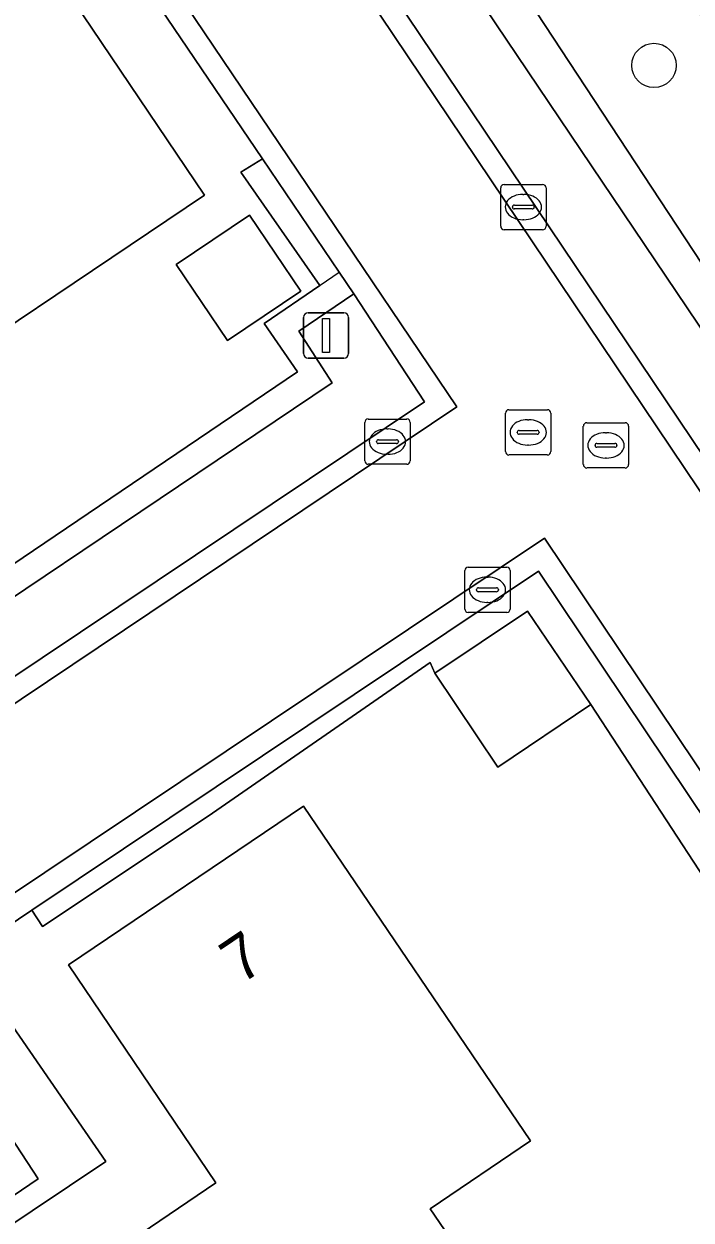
# Model space of a CAD drawing. Extents: x 158793 to 159888, y 384317 to 385256.
# Drawn here: x 158930.48 to 158945.21, y 384617.61 to 384644.03 of the extents above; entities that cross this region are included whole.
import ezdxf

# ---------------------------------------------------------------- set-up
doc = ezdxf.new("R2010")
doc.units = 0
for name, color, linetype in [('IMGEO_Boom', 7, 'Continuous'), ('IMGEO_Erf', 7, 'Continuous'), ('IMGEO_Groenvoorziening', 7, 'Continuous'), ('IMGEO_Haag', 7, 'Continuous'), ('IMGEO_Hek', 7, 'Continuous'), ('IMGEO_Kolk', 7, 'Continuous'), ('IMGEO_Lichtmast', 7, 'Continuous'), ('IMGEO_Pand', 7, 'Continuous'), ('IMGEO_Pand_nummerreeks', 7, 'Continuous'), ('IMGEO_Parkeervlak_open', 7, 'Continuous'), ('IMGEO_Rijbaan_lokaal_open', 7, 'Continuous'), ('IMGEO_Rioolput', 7, 'Continuous'), ('IMGEO_Voetpad_open', 7, 'Continuous')]:
    doc.layers.add(name, color=color, linetype=linetype)

msp = doc.modelspace()

# ---------------------------------------------------------------- linework, layer by layer
at = {"layer": 'IMGEO_Boom'}
msp.add_circle((158944.39, 384643.118), 0.489, dxfattribs=at)
at = {"layer": 'IMGEO_Erf'}
for points in [[(158935.269, 384640.755), (158935.742, 384641.055), (158931.239, 384647.707), (158930.053, 384646.895), (158926.376, 384644.46), (158920.02, 384653.654), (158917.65, 384657.141), (158903.486, 384647.632), (158905.26, 384644.832), (158899.805, 384640.906), (158909.685, 384626.219), (158910.802, 384626.858), (158911.256, 384626.177), (158922.042, 384633.454), (158922.226, 384633.163), (158925.099, 384628.623), (158936.517, 384636.347), (158935.783, 384637.416), (158937.012, 384638.256)], [(158933.838, 384638.715), (158935.46, 384639.808), (158936.59, 384638.131), (158934.968, 384637.038)]]:
    msp.add_lwpolyline(points, close=True, dxfattribs=at)
for points in [[(158924.575, 384644.51), (158926.138, 384642.19), (158930.948, 384645.466), (158934.462, 384640.251), (158927.06, 384635.272), (158926.167, 384636.6), (158925.827, 384636.371), (158925.241, 384637.242), (158922.204, 384635.199), (158920.865, 384637.19), (158919.342, 384636.067), (158919.879, 384635.339), (158916.324, 384632.791), (158915.823, 384633.472), (158915.091, 384632.933), (158913.616, 384635.123), (158911.211, 384633.503), (158907.976, 384638.304), (158904.737, 384643.112), (158907.129, 384644.742)], [(158948.959, 384619.868), (158942.998, 384628.997), (158940.94, 384627.612), (158939.55, 384629.69), (158939.449, 384629.925), (158934.543, 384626.53), (158930.884, 384624.093), (158930.65, 384624.451), (158929.151, 384623.447), (158932.282, 384618.903), (158921.737, 384611.84)], [(158932.239, 384616.753), (158934.715, 384618.426), (158931.463, 384623.249), (158936.651, 384626.748), (158941.663, 384619.361), (158939.449, 384617.854), (158941.719, 384614.519)]]:
    msp.add_lwpolyline(points, dxfattribs=at)
at = {"layer": 'IMGEO_Groenvoorziening'}
for points in [[(158939.017, 384653.792), (158935.807, 384651.605), (158936.203, 384651.016), (158937.049, 384651.521), (158951.101, 384630.138), (158952.761, 384631.247), (158949.979, 384635.355), (158950.928, 384636.006)], [(158936.203, 384651.016), (158950.52, 384629.75), (158951.101, 384630.138), (158937.049, 384651.521)], [(158937.281, 384636.103), (158936.543, 384637.243), (158937.764, 384638.068), (158937.439, 384638.548), (158935.742, 384641.055), (158935.269, 384640.755), (158937.012, 384638.256), (158935.783, 384637.416), (158936.517, 384636.347), (158925.099, 384628.623), (158925.43, 384628.137)], [(158954.158, 384623.366), (158953.415, 384624.464), (158948.9, 384621.402), (158941.838, 384631.945), (158930.65, 384624.451), (158930.884, 384624.093), (158934.543, 384626.53), (158939.449, 384629.925), (158939.55, 384629.69), (158941.596, 384631.059), (158942.998, 384628.997), (158948.959, 384619.868)], [(158919.186, 384616.765), (158918.336, 384616.199), (158921.296, 384611.545), (158921.737, 384611.84), (158932.282, 384618.903), (158929.151, 384623.447), (158928.046, 384622.707), (158930.79, 384618.521), (158925.79, 384615.12), (158922.031, 384612.574)]]:
    msp.add_lwpolyline(points, close=True, dxfattribs=at)
at = {"layer": 'IMGEO_Haag'}
for points in [[(158936.203, 384651.016), (158950.52, 384629.75), (158951.101, 384630.138), (158937.049, 384651.521)], [(158954.158, 384623.366), (158953.415, 384624.464), (158948.9, 384621.402), (158941.838, 384631.945), (158930.65, 384624.451), (158930.884, 384624.093), (158934.543, 384626.53), (158939.449, 384629.925), (158939.55, 384629.69), (158941.596, 384631.059), (158942.998, 384628.997), (158948.959, 384619.868)]]:
    msp.add_lwpolyline(points, close=True, dxfattribs=at)
at = {"layer": 'IMGEO_Hek'}
for points in [[(158905.26, 384644.832), (158899.805, 384640.906), (158909.685, 384626.219), (158910.802, 384626.858), (158911.256, 384626.177), (158922.042, 384633.454), (158922.226, 384633.163), (158925.099, 384628.623), (158936.517, 384636.347), (158935.783, 384637.416)], [(158935.783, 384637.416), (158937.439, 384638.548)]]:
    msp.add_lwpolyline(points, dxfattribs=at)
at = {"layer": 'IMGEO_Kolk'}
for p, q in [((158941.004, 384639.562), (158941.004, 384640.414)), ((158941.079, 384640.488), (158941.931, 384640.488)), ((158942.005, 384640.414), (158942.005, 384639.562)), ((158941.492, 384640.268), (158941.517, 384640.268)), ((158941.263, 384639.982), (158941.263, 384639.994)), ((158941.701, 384639.945), (158941.303, 384639.945)), ((158941.306, 384640.031), (158941.704, 384640.031)), ((158941.747, 384639.994), (158941.747, 384639.982)), ((158941.515, 384639.708), (158941.49, 384639.708)), ((158941.931, 384639.488), (158941.079, 384639.488)), ((158938.078, 384635.305), (158938.93, 384635.305)), ((158938.003, 384634.379), (158938.003, 384635.231)), ((158938.491, 384635.085), (158938.516, 384635.085)), ((158939.004, 384635.231), (158939.004, 384634.379)), ((158938.262, 384634.799), (158938.262, 384634.811)), ((158938.7, 384634.762), (158938.302, 384634.762)), ((158938.305, 384634.848), (158938.703, 384634.848)), ((158938.746, 384634.811), (158938.746, 384634.799)), ((158938.514, 384634.525), (158938.489, 384634.525)), ((158938.93, 384634.305), (158938.078, 384634.305)), ((158940.211, 384631.107), (158940.211, 384631.959)), ((158940.286, 384632.033), (158941.138, 384632.033)), ((158941.212, 384631.959), (158941.212, 384631.107)), ((158940.699, 384631.813), (158940.724, 384631.813)), ((158940.47, 384631.527), (158940.47, 384631.539)), ((158940.908, 384631.49), (158940.51, 384631.49)), ((158940.513, 384631.576), (158940.911, 384631.576)), ((158940.954, 384631.539), (158940.954, 384631.527)), ((158940.722, 384631.253), (158940.697, 384631.253)), ((158941.138, 384631.033), (158940.286, 384631.033))]:
    msp.add_line(p, q, dxfattribs=at)
for points in [[(158941.004, 384639.562), (158941.004, 384640.414)], [(158941.079, 384640.488), (158941.931, 384640.488)], [(158942.005, 384640.414), (158942.005, 384639.562)], [(158941.931, 384639.488), (158941.079, 384639.488)], [(158938.078, 384635.305), (158938.93, 384635.305)], [(158938.003, 384634.379), (158938.003, 384635.231)], [(158939.004, 384635.231), (158939.004, 384634.379)], [(158938.93, 384634.305), (158938.078, 384634.305)], [(158940.211, 384631.107), (158940.211, 384631.959)], [(158940.286, 384632.033), (158941.138, 384632.033)], [(158941.212, 384631.959), (158941.212, 384631.107)], [(158941.138, 384631.033), (158940.286, 384631.033)]]:
    msp.add_lwpolyline(points, dxfattribs=at)
for centre, radius, start, end in [((158941.081, 384640.412), 0.0765, 91.552, 178.448), ((158941.081, 384640.412), 0.0765, 91.552, 178.448), ((158941.929, 384640.412), 0.0765, 1.552, 88.448), ((158941.929, 384640.412), 0.0765, 1.552, 88.448), ((158941.303, 384639.991), 0.0403, 85.8775, 175.7526), ((158941.3, 384639.981), 0.0366, 178.938, 274.7102), ((158941.704, 384639.988), 0.043, 264.8664, 352.4533), ((158941.708, 384639.993), 0.0386, 1.7309, 96.639), ((158941.081, 384639.564), 0.0765, 181.552, 268.448), ((158941.081, 384639.564), 0.0765, 181.552, 268.448), ((158941.929, 384639.564), 0.0765, 271.552, 358.448), ((158941.929, 384639.564), 0.0765, 271.552, 358.448), ((158938.08, 384635.229), 0.0765, 91.552, 178.448), ((158938.08, 384635.229), 0.0765, 91.552, 178.448), ((158938.928, 384635.229), 0.0765, 1.552, 88.448), ((158938.928, 384635.229), 0.0765, 1.552, 88.448), ((158938.302, 384634.808), 0.0403, 85.8775, 175.7526), ((158938.299, 384634.798), 0.0366, 178.938, 274.7102), ((158938.703, 384634.805), 0.043, 264.8664, 352.4533), ((158938.707, 384634.81), 0.0386, 1.7309, 96.639), ((158938.08, 384634.381), 0.0765, 181.552, 268.448), ((158938.08, 384634.381), 0.0765, 181.552, 268.448), ((158938.928, 384634.381), 0.0765, 271.552, 358.448), ((158938.928, 384634.381), 0.0765, 271.552, 358.448), ((158940.288, 384631.957), 0.0765, 91.552, 178.448), ((158940.288, 384631.957), 0.0765, 91.552, 178.448), ((158941.136, 384631.957), 0.0765, 1.552, 88.448), ((158941.136, 384631.957), 0.0765, 1.552, 88.448), ((158940.51, 384631.536), 0.0403, 85.8775, 175.7526), ((158940.507, 384631.526), 0.0366, 178.938, 274.7102), ((158940.911, 384631.533), 0.043, 264.8664, 352.4533), ((158940.915, 384631.538), 0.0386, 1.7309, 96.639), ((158940.288, 384631.109), 0.0765, 181.552, 268.448), ((158940.288, 384631.109), 0.0765, 181.552, 268.448), ((158941.136, 384631.109), 0.0765, 271.552, 358.448), ((158941.136, 384631.109), 0.0765, 271.552, 358.448)]:
    msp.add_arc(centre, radius, start, end, dxfattribs=at)
for centre, major_axis, ratio, start_param, end_param in [((158941.491, 384639.988), (-0.387, 0.002), 0.722429, 4.712389, 7.853982), ((158941.516, 384639.988), (-0.39, 0.002), 0.717154, 1.570796, 4.712389), ((158938.49, 384634.805), (-0.387, 0.002), 0.722429, 4.712389, 7.853982), ((158938.515, 384634.805), (-0.39, 0.002), 0.717154, 1.570796, 4.712389), ((158940.698, 384631.533), (-0.387, 0.002), 0.722429, 4.712389, 7.853982), ((158940.723, 384631.533), (-0.39, 0.002), 0.717154, 1.570796, 4.712389)]:
    msp.add_ellipse(centre, major_axis=major_axis, ratio=ratio, start_param=start_param, end_param=end_param, dxfattribs=at)
at = {"layer": 'IMGEO_Lichtmast'}
for p, q in [((158936.652, 384636.751), (158936.652, 384637.551)), ((158936.652, 384637.551), (158936.652, 384636.751)), ((158936.752, 384637.651), (158937.542, 384637.651)), ((158937.542, 384637.651), (158936.752, 384637.651)), ((158937.642, 384637.551), (158937.642, 384636.751)), ((158937.642, 384636.751), (158937.642, 384637.551)), ((158937.542, 384636.651), (158936.752, 384636.651)), ((158936.752, 384636.651), (158937.542, 384636.651))]:
    msp.add_line(p, q, dxfattribs=at)
msp.add_lwpolyline([(158937.072, 384637.526), (158937.222, 384637.526), (158937.222, 384636.776), (158937.072, 384636.776), (158937.072, 384637.526)], dxfattribs=at)
for centre, start, end in [((158936.752, 384637.551), 90, 180), ((158936.752, 384637.551), 90, 180), ((158937.542, 384637.551), 0, 90), ((158937.542, 384637.551), 360, 90), ((158936.752, 384636.751), 180, 270), ((158936.752, 384636.751), 180, 270), ((158937.542, 384636.751), 270, 0), ((158937.542, 384636.751), 270, 0)]:
    msp.add_arc(centre, 0.1, start, end, dxfattribs=at)
at = {"layer": 'IMGEO_Pand'}
for points in [[(158930.948, 384645.466), (158926.138, 384642.19), (158924.575, 384644.51), (158918.797, 384640.665), (158921.037, 384637.317), (158920.865, 384637.19), (158922.204, 384635.199), (158925.241, 384637.242), (158925.827, 384636.371), (158926.167, 384636.6), (158927.06, 384635.272), (158934.462, 384640.251)], [(158933.838, 384638.715), (158934.968, 384637.038), (158936.59, 384638.131), (158935.46, 384639.808)], [(158941.596, 384631.059), (158939.55, 384629.69), (158940.94, 384627.612), (158942.998, 384628.997)], [(158931.463, 384623.249), (158934.715, 384618.426), (158932.239, 384616.753), (158936.087, 384611.18), (158939.564, 384613.58), (158939.81, 384613.244), (158941.719, 384614.519), (158939.449, 384617.854), (158941.663, 384619.361), (158936.651, 384626.748)]]:
    msp.add_lwpolyline(points, close=True, dxfattribs=at)
at = {"layer": 'IMGEO_Parkeervlak_open'}
msp.add_lwpolyline([(158928.046, 384622.707), (158919.186, 384616.765), (158922.031, 384612.574), (158925.79, 384615.12), (158930.79, 384618.521)], close=True, dxfattribs=at)
at = {"layer": 'IMGEO_Rijbaan_lokaal_open'}
for points in [[(158920.881, 384670.173), (158923.955, 384665.633), (158949.957, 384626.932), (158968.418, 384639.524), (158968.134, 384639.947), (158950.085, 384627.638), (158924.353, 384665.905), (158921.285, 384670.455)], [(158941.972, 384632.67), (158949.064, 384622.099), (158970.35, 384636.65), (158968.418, 384639.524), (158949.957, 384626.932), (158923.955, 384665.633), (158920.881, 384670.173)], [(158920.527, 384663.541), (158921.052, 384662.795), (158921.38, 384662.329), (158923.499, 384659.163), (158924.01, 384658.409), (158927.045, 384653.945), (158927.544, 384653.21), (158930.702, 384648.501), (158931.239, 384647.707), (158935.742, 384641.055), (158937.439, 384638.548), (158937.764, 384638.068), (158939.325, 384635.681), (158916.548, 384620.432), (158916.491, 384620.393), (158916.788, 384619.978), (158916.847, 384620.015), (158940.033, 384635.577), (158921.019, 384663.762)], [(158921.019, 384663.762), (158940.033, 384635.577), (158916.847, 384620.015), (158916.788, 384619.978), (158918.623, 384617.027), (158918.871, 384617.212), (158941.972, 384632.67)]]:
    msp.add_lwpolyline(points, dxfattribs=at)
msp.add_lwpolyline([(158941.972, 384632.67), (158918.871, 384617.212), (158919.186, 384616.765), (158928.046, 384622.707), (158929.151, 384623.447), (158930.65, 384624.451), (158941.838, 384631.945), (158948.9, 384621.402), (158953.415, 384624.464), (158955.406, 384625.815), (158956.071, 384626.266), (158960.669, 384629.404), (158961.404, 384629.901), (158968.085, 384634.504), (158968.774, 384634.969), (158970.621, 384636.247), (158970.35, 384636.65), (158949.064, 384622.099)], close=True, dxfattribs=at)
at = {"layer": 'IMGEO_Rioolput'}
for p, q in [((158941.111, 384634.584), (158941.111, 384635.436)), ((158941.186, 384635.51), (158942.038, 384635.51)), ((158941.599, 384635.29), (158941.624, 384635.29)), ((158942.112, 384635.436), (158942.112, 384634.584)), ((158941.413, 384635.053), (158941.811, 384635.053)), ((158942.829, 384634.297), (158942.829, 384635.149)), ((158942.904, 384635.223), (158943.756, 384635.223)), ((158943.83, 384635.149), (158943.83, 384634.297)), ((158941.37, 384635.004), (158941.37, 384635.016)), ((158941.808, 384634.967), (158941.41, 384634.967)), ((158941.854, 384635.016), (158941.854, 384635.004)), ((158943.131, 384634.766), (158943.529, 384634.766)), ((158943.317, 384635.003), (158943.342, 384635.003)), ((158942.038, 384634.51), (158941.186, 384634.51)), ((158941.622, 384634.73), (158941.597, 384634.73)), ((158943.088, 384634.717), (158943.088, 384634.729)), ((158943.526, 384634.68), (158943.128, 384634.68)), ((158943.572, 384634.729), (158943.572, 384634.717)), ((158943.34, 384634.443), (158943.315, 384634.443)), ((158943.756, 384634.223), (158942.904, 384634.223))]:
    msp.add_line(p, q, dxfattribs=at)
for points in [[(158941.111, 384634.584), (158941.111, 384635.436)], [(158941.186, 384635.51), (158942.038, 384635.51)], [(158942.112, 384635.436), (158942.112, 384634.584)], [(158942.829, 384634.297), (158942.829, 384635.149)], [(158942.904, 384635.223), (158943.756, 384635.223)], [(158943.83, 384635.149), (158943.83, 384634.297)], [(158942.038, 384634.51), (158941.186, 384634.51)], [(158943.756, 384634.223), (158942.904, 384634.223)]]:
    msp.add_lwpolyline(points, dxfattribs=at)
for centre, radius, start, end in [((158941.188, 384635.434), 0.0765, 91.552, 178.448), ((158941.188, 384635.434), 0.0765, 91.552, 178.448), ((158942.036, 384635.434), 0.0765, 1.552, 88.448), ((158942.036, 384635.434), 0.0765, 1.552, 88.448), ((158941.41, 384635.013), 0.0403, 85.8775, 175.7526), ((158941.815, 384635.015), 0.0386, 1.7309, 96.639), ((158942.906, 384635.147), 0.0765, 91.552, 178.448), ((158942.906, 384635.147), 0.0765, 91.552, 178.448), ((158943.754, 384635.147), 0.0765, 1.552, 88.448), ((158943.754, 384635.147), 0.0765, 1.552, 88.448), ((158941.407, 384635.003), 0.0366, 178.938, 274.7102), ((158941.811, 384635.01), 0.043, 264.8664, 352.4533), ((158943.128, 384634.726), 0.0403, 85.8775, 175.7526), ((158943.533, 384634.728), 0.0386, 1.7309, 96.639), ((158941.188, 384634.586), 0.0765, 181.552, 268.448), ((158941.188, 384634.586), 0.0765, 181.552, 268.448), ((158942.036, 384634.586), 0.0765, 271.552, 358.448), ((158942.036, 384634.586), 0.0765, 271.552, 358.448), ((158943.125, 384634.716), 0.0366, 178.938, 274.7102), ((158943.529, 384634.723), 0.043, 264.8664, 352.4533), ((158942.906, 384634.299), 0.0765, 181.552, 268.448), ((158942.906, 384634.299), 0.0765, 181.552, 268.448), ((158943.754, 384634.299), 0.0765, 271.552, 358.448), ((158943.754, 384634.299), 0.0765, 271.552, 358.448)]:
    msp.add_arc(centre, radius, start, end, dxfattribs=at)
for centre, major_axis, ratio, start_param, end_param in [((158941.598, 384635.01), (-0.387, 0.002), 0.722429, 4.712389, 7.853982), ((158941.623, 384635.01), (-0.39, 0.002), 0.717154, 1.570796, 4.712389), ((158943.316, 384634.723), (-0.387, 0.002), 0.722429, 4.712389, 7.853982), ((158943.341, 384634.723), (-0.39, 0.002), 0.717154, 1.570796, 4.712389)]:
    msp.add_ellipse(centre, major_axis=major_axis, ratio=ratio, start_param=start_param, end_param=end_param, dxfattribs=at)
at = {"layer": 'IMGEO_Voetpad_open'}
for points in [[(158921.285, 384670.455), (158924.353, 384665.905), (158950.085, 384627.638), (158968.134, 384639.947), (158964.327, 384645.61), (158962.382, 384644.283), (158965.367, 384639.89), (158964.741, 384639.472), (158960.089, 384636.266), (158959.328, 384635.75), (158952.761, 384631.247), (158951.101, 384630.138), (158950.52, 384629.75), (158936.203, 384651.016), (158935.807, 384651.605), (158931.31, 384658.301), (158930.791, 384659.038), (158926.191, 384665.854), (158925.456, 384666.95), (158924.962, 384667.694), (158922.109, 384671.989)], [(158939.325, 384635.681), (158937.764, 384638.068), (158936.543, 384637.243), (158937.281, 384636.103), (158925.43, 384628.137), (158924.728, 384627.665), (158915.86, 384621.72), (158915.141, 384621.25), (158914.37, 384620.747)], [(158915.538, 384619.745), (158916.491, 384620.393), (158916.548, 384620.432), (158939.325, 384635.681)]]:
    msp.add_lwpolyline(points, dxfattribs=at)

# ---------------------------------------------------------------- texts
at = {"layer": 'IMGEO_Pand_nummerreeks'}
msp.add_text('7', height=1, rotation=33.9981, dxfattribs=at).set_placement((158935.264, 384622.797))

doc.saveas('drawing.dxf')
